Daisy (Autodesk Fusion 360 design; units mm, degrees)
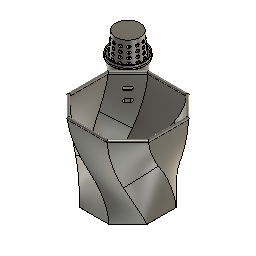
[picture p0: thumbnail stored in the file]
parameter "wall" = 1.35
parameter "height" = 77 (= "Size * 0.7") comment "Vase Hight (Medium setting)"
parameter "tolerance" = 0.15
sketch "Sketch1" plane through (0, 0, 0) normal (0, 0, 1) x axis (1, 0, 0)
  line L1 (-56.3193, -56.3193) -> (56.3193, -56.3193)
  line L2 (-56.3193, 56.3193) -> (-56.3193, -56.3193)
  line L3 (56.3193, 56.3193) -> (-56.3193, 56.3193)
  line L4 (56.3193, -56.3193) -> (56.3193, 56.3193)
  line L5 (-56.3193, 56.3193) -> (56.3193, -56.3193)
  line L6 (56.3193, 56.3193) -> (-56.3193, -56.3193)
  line L7 (-52.7837, 59.8548) -> (59.8548, -52.7837)
  line L8 (-59.8548, 52.7837) -> (52.7837, -59.8548)
  line L9 (-44.8807, -1.3193) -> (1.3193, 44.8807)
  line L10 (1.3193, -47.5193) -> (-44.8807, -1.3193)
  line L11 (47.5193, -1.3193) -> (1.3193, -47.5193)
  line L12 (1.3193, 44.8807) -> (47.5193, -1.3193)
  line L13 (1.3193, -47.5193) -> (1.3193, 44.8807)
  line L14 (47.5193, -1.3193) -> (-44.8807, -1.3193)
  line L15 (1.3193, 56.3193) -> (1.3193, -1.3193)
  line L16 (4.8548, 2.2163) -> (-2.2163, -4.8548)
  line L17 (-37.7837, 44.8548) -> (-44.8548, 37.7837)
  circle C1 centre (1.3193, -1.3193) radius 55
  circle C2 centre (-41.3193, 41.3193) radius 15
  circle C3 centre (1.3193, -1.3193) radius 46.2
  circle C4 centre (-41.3193, 41.3193) radius 13.65
  circle C5 centre (-41.3193, 41.3193) radius 13.5
  circle C6 centre (1.3193, -1.3193) radius 45.3
  point P6 (0, 0)
  point P1 (0, 0)
  point P7 (1.3193, -1.3193)
  point P8 (-41.3193, 41.3193)
  point P9 (1.3193, -1.3193)
  point P19 (1.3193, -1.3193)
  point P15 (1.3193, 44.8807)
  point P20 (1.3193, -1.3193)
  point P21 (1.3193, 56.3193)
  point P22 (-2.2163, -4.8548)
  point P23 (4.8548, 2.2163)
  point P26 (1.3193, -1.3193)
  point P27 (-44.8548, 37.7837)
  point P28 (-37.7837, 44.8548)
  point P24 (-41.3193, 41.3193)
  horizontal L1
  perpendicular L1 L2
  parallel L1 L3
  parallel L2 L4
  coincident L5 P6
  coincident L6 P6
  coincident P1 P6
  coincident L5 P7
  coincident L5 P8
  tangent L3 C2
  tangent L4 C1
  coincident P7 P9
  perpendicular L9 L10
  parallel L9 L11
  parallel L10 L12
  coincident L13 P19
  coincident L14 P19
  coincident P9 P19
  equal L9 L12
  coincident C3 P15
  coincident P9 P20
  coincident L3 P21
  perpendicular L3 L15
  coincident L8 P22
  coincident L7 P23
  perpendicular L7 L16
  equal L2 L3
  midpoint P19 L16
  coincident P19 P26
  tangent C2 C6
  coincident L8 P27
  coincident L7 P28
  perpendicular L7 L17
  coincident P24 L17
  dimension "Size" diameter C1 = 110
  dimension "d5" diameter C2 = 30
  dimension "d8" = 5
  dimension "d9" = -5
  dimension "d16" = -8.8 (= "-Size * 0.08")
  dimension "d17" angle L13 L15 = 0
  dimension "d81" distance P7 P8 = 60.3 (= "Size * 0.45 + ( wall * 8 )")
work_plane "WorkPlane1" AlongDistance 38.5 (= "height / 2")
work_plane "WorkPlane2" AlongDistance 77 (= "height")
work_plane "WorkPlane5" AlongDistance 46.2 (= "height * 0.6")
work_plane "WorkPlane4" RotateAngle 90
sketch "Sketch2" plane through (0, 0, 38.5) normal (0, 0, 1) x axis (1, 0, 0)
  line L1 (1.3193, 53.6807) -> (1.3193, -1.3193)
  line L2 (-40.5964, 22.8807) -> (25.5193, 40.5964)
  line L3 (-22.8807, -43.2349) -> (-40.5964, 22.8807)
  line L4 (43.2349, -25.5193) -> (-22.8807, -43.2349)
  line L5 (25.5193, 40.5964) -> (43.2349, -25.5193)
  line L6 (-22.8807, -43.2349) -> (25.5193, 40.5964)
  line L7 (43.2349, -25.5193) -> (-40.5964, 22.8807)
  circle C1 centre (1.3193, -1.3193) radius 55
  circle C2 centre (1.3193, -1.3193) radius 48.4
  point P2 (1.3193, -1.3193)
  point P4 (1.3193, -1.3193)
  point P5 (1.3193, 53.6807)
  point P10 (1.3193, -1.3193)
  point P6 (25.5193, 40.5964)
  coincident P2 P4
  coincident C1 P5
  vertical L1
  perpendicular L2 L3
  parallel L2 L4
  parallel L3 L5
  coincident L6 P10
  coincident L7 P10
  coincident P2 P10
  equal L2 L5
  coincident C2 P6
  dimension "d14" = -6.6 (= "-Size * 0.06")
  dimension "d15" angle L1 L6 = 30
sketch "Sketch3" plane through (0, 0, 77) normal (0, 0, 1) x axis (1, 0, 0)
  line L1 (-37.5716, 37.5716) -> (40.2101, 37.5716)
  line L2 (-37.5716, -40.2101) -> (-37.5716, 37.5716)
  line L3 (40.2101, -40.2101) -> (-37.5716, -40.2101)
  line L4 (40.2101, 37.5716) -> (40.2101, -40.2101)
  line L5 (-37.5716, -40.2101) -> (40.2101, 37.5716)
  line L6 (40.2101, -40.2101) -> (-37.5716, 37.5716)
  line L7 (1.3193, 53.6807) -> (1.3193, -1.3193)
  circle C1 centre (1.3193, -1.3193) radius 55
  circle C2 centre (-41.3193, 41.3193) radius 15
  circle C3 centre (-41.3193, 41.3193) radius 7.5
  point P7 (1.3193, -1.3193)
  point P2 (1.3193, -1.3193)
  point P3 (40.2101, 37.5716)
  point P8 (1.3193, -1.3193)
  point P9 (1.3193, 53.6807)
  perpendicular L1 L2
  parallel L1 L3
  parallel L2 L4
  coincident L5 P7
  coincident L6 P7
  coincident P2 P7
  equal L1 L4
  coincident C1 P3
  coincident P2 P8
  coincident C1 P9
  vertical L7
  concentric C2 C3
  dimension "d18" angle L5 L7 = 45
  dimension "d126" diameter C3 = 15
sketch "Sketch9" plane through (0, 0, 46.2) normal (0, 0, 1) x axis (1, 0, 0)
  circle C1 centre (-41.3193, 41.3193) radius 13.65
  circle C2 centre (-41.3193, 41.3193) radius 11
  concentric C1 C2
  dimension "d127" diameter C2 = 22
loft "Loft2" sketch "Sketch1" + "Sketch9" + "Sketch3" Start Weight 4.0298 Start TakeOff Angle 0 End Weight -3.9427 End TakeOff Angle 0
loft "Loft1" sketch "Sketch1" + "Sketch2" + "Sketch3" Start Weight 1.991 Start TakeOff Angle 0 End Weight -1.8239 End TakeOff Angle 0
chamfer "Chamfer4" distance 19.8 (= "Size * 0.18")
extrude "Extrude2" new body sketch "Sketch1" profile of C1 C2 L7 L8 C3 L9 L10 L16 C4 C5 C6 L17 blind 15 from offset 3
extrude "Extrude3" sketch "Sketch1" profile of C1 C2 L7 L8 C3 L9 L10 L16 C4 C5 C6 L17 blind -15 from offset -10
chamfer "Chamfer1" distance 1.35 (= "wall")
fillet "Fillet1" radius 3
extrude "Extrude17" sketch "Sketch1" profile of C1 L7 L8 C5 blind 20 taper -5
shell "Shell1" innerThickness 1.35 (= "wall")
extrude "Extrude18" add sketch "Sketch1" profile of C1 C2 L7 L8 C4 C5 along normal blind 20 taper -3
extrude "Extrude16" cut sketch "Sketch1" profile of C1 L7 L8 C4 C5 along normal blind 20 taper -5
offset_faces "OffsetFaces5" distance 1.35 (= "wall")
sketch "Sketch6" plane through (0, 0, 77) normal (0, 0, 1) x axis (-1, 0, 0)
  line L1 (41.3193, -24.8193) -> (41.3193, -57.8193)
  line L2 (33.6513, -26.7092) -> (48.9872, -55.9293)
  line L3 (27.74, -31.9462) -> (54.8985, -50.6923)
  line L4 (24.9396, -39.3304) -> (57.699, -43.3081)
  line L5 (25.8915, -47.1703) -> (56.747, -35.4683)
  line L6 (30.3777, -53.6697) -> (52.2608, -28.9688)
  line L7 (37.3706, -57.3398) -> (45.268, -25.2987)
  line L8 (45.268, -57.3398) -> (37.3706, -25.2987)
  line L9 (52.2608, -53.6697) -> (30.3777, -28.9688)
  line L10 (56.747, -47.1703) -> (25.8915, -35.4683)
  line L11 (57.699, -39.3304) -> (24.9396, -43.3081)
  line L12 (54.8985, -31.9462) -> (27.74, -50.6923)
  line L13 (48.9872, -26.7092) -> (33.6513, -55.9293)
  circle C1 centre (41.3193, -41.3193) radius 15.15
  circle C2 centre (41.3193, -41.3193) radius 16.5
  circle C3 centre (41.3193, -41.3193) radius 12.3
  circle C4 centre (41.3193, -41.3193) radius 15
  circle C5 centre (41.3193, -41.3193) radius 13.65
  point P5 (41.3193, -57.8193)
  point P6 (41.3193, -24.8193)
  point P3 (41.3193, -41.3193)
  coincident C2 P5
  coincident C2 P6
  vertical L1
  coincident P3 L1
  concentric C2 C4
  concentric C3 C5
  dimension "d115" distance C1 C2 = 1.35 (= "wall")
  dimension "d140" distance C1 C4 = 0.15 (= "tolerance")
  dimension "d141" distance C3 C5 = 1.35 (= "wall")
  dimension "d74" C-Pattern1-Angle = 360
extrude "Extrude7" add sketch "Sketch6" profile of C1 C2 C3 L1 L2 L3 L4 L5 L6 L7 L8 L9 L10 L11 L12 L13 no distance stored
extrude "Extrude6" add sketch "Sketch6" profile of C1 C2 L1 L2 L3 L4 L5 L6 L7 L8 L9 L10 L11 L12 L13 along normal blind 2 taper -5
extrude "Extrude8" cut sketch "Sketch6" profile of C3 L1 L2 L3 L4 L5 L6 L7 L8 L9 L10 L11 L12 L13 C5 along normal blind 2.5
rectangular_pattern "R-Pattern1" uSpaceDistance 4.5 vSpaceDistance 0
chamfer "Chamfer5" distance 0.8
circular_pattern "C-Pattern1" countU 13 TotalAngle 360
chamfer "Chamfer7" distance 2.7 (= "wall * 2") distance 1.5 (= "wall + tolerance")
sketch "Sketch7" plane through (1.3193, -1.3193, 0) normal (0.7071, -0.7071, 0) x axis (0.7071, 0.7071, 0)
  line L1 (3.65, 6) -> (3.65, 15)
  line L2 (-3.65, 15) -> (-3.65, 6)
  line L3 (5, 15) -> (5, 6)
  line L4 (-5, 6) -> (-5, 15)
  line L5 (-3.65, 64) -> (-3.65, 55)
  line L6 (3.65, 55) -> (3.65, 64)
  line L7 (5, 64) -> (5, 55)
  line L8 (-5, 55) -> (-5, 64)
  line L9 (-2, 4.35) -> (2, 4.35)
  line L10 (2, 16.65) -> (-2, 16.65)
  line L11 (2, 3) -> (-2, 3)
  line L12 (-2, 18) -> (2, 18)
  line L13 (-2, 53.35) -> (2, 53.35)
  line L14 (2, 65.65) -> (-2, 65.65)
  line L15 (-2, 67) -> (2, 67)
  line L16 (2, 52) -> (-2, 52)
  line L17 (2, 55) -> (-2, 64)
  line L18 (2, 6) -> (-2, 15)
  line L19 (2, 62.35) -> (-2, 62.35)
  line L20 (2, 56.65) -> (-2, 56.65)
  line L21 (2, 13.35) -> (-2, 13.35)
  line L22 (2, 7.65) -> (-2, 7.65)
  arc A1 centre (-2, 6) radius 1.65 clockwise from (-2, 4.35) to (-3.65, 6)
  arc A2 centre (-2, 15) radius 1.65 clockwise from (-3.65, 15) to (-2, 16.65)
  arc A3 centre (-2, 6) radius 3 clockwise from (-2, 3) to (-5, 6)
  arc A4 centre (-2, 15) radius 3 clockwise from (-5, 15) to (-2, 18)
  arc A5 centre (2, 55) radius 1.65 clockwise from (3.65, 55) to (2, 53.35)
  arc A6 centre (2, 64) radius 1.65 clockwise from (2, 65.65) to (3.65, 64)
  arc A7 centre (2, 55) radius 3 clockwise from (5, 55) to (2, 52)
  arc A8 centre (2, 64) radius 3 clockwise from (2, 67) to (5, 64)
  arc A9 centre (2, 6) radius 1.65 clockwise from (3.65, 6) to (2, 4.35)
  arc A10 centre (2, 15) radius 1.65 clockwise from (2, 16.65) to (3.65, 15)
  arc A11 centre (2, 6) radius 3 clockwise from (5, 6) to (2, 3)
  arc A12 centre (2, 15) radius 3 clockwise from (2, 18) to (5, 15)
  arc A13 centre (-2, 55) radius 1.65 clockwise from (-2, 53.35) to (-3.65, 55)
  arc A14 centre (-2, 64) radius 1.65 clockwise from (-3.65, 64) to (-2, 65.65)
  arc A15 centre (-2, 64) radius 3 clockwise from (-5, 64) to (-2, 67)
  arc A16 centre (-2, 55) radius 3 clockwise from (-2, 52) to (-5, 55)
  circle C1 centre (2, 64) radius 1.65
  circle C2 centre (-2, 64) radius 1.65
  circle C3 centre (-2, 55) radius 1.65
  circle C4 centre (2, 55) radius 1.65
  circle C5 centre (0, 59.5) radius 1.65
  circle C6 centre (2, 15) radius 1.65
  circle C7 centre (-2, 15) radius 1.65
  circle C8 centre (-2, 6) radius 1.65
  circle C9 centre (2, 6) radius 1.65
  circle C10 centre (0, 10.5) radius 1.65
  point P39 (-2, 64)
  point P42 (-2, 64)
  point P20 (2, 55)
  point P43 (2, 55)
  point P19 (-2, 15)
  point P44 (-2, 15)
  point P27 (2, 6)
  point P45 (2, 6)
  point P49 (2, 55)
  point P50 (0, 59.5)
  point P52 (-2, 15)
  point P54 (2, 6)
  point P55 (0, 10.5)
  point P56 (-2, 62.35)
  point P57 (2, 62.35)
  point P58 (-2, 56.65)
  point P59 (2, 56.65)
  point P60 (-2, 13.35)
  point P61 (2, 13.35)
  point P62 (-2, 7.65)
  point P63 (2, 7.65)
  point P11 (2, 65.65)
  point P18 (-2, 6)
  point P53 (-2, 6)
  coincident P39 P42
  coincident P20 P43
  coincident P19 P44
  coincident P27 P45
  concentric A6 C1
  concentric A14 C2
  concentric A13 C3
  coincident P43 P49
  midpoint L17 P50
  concentric A10 C6
  coincident P44 P52
  coincident P45 P54
  midpoint L18 P55
  equal C1 C2
  equal C1 C5
  equal C1 C4
  equal C1 C3
  equal C1 C6
  equal C1 C7
  equal C1 C10
  equal C1 C9
  equal C1 C8
  coincident C2 P56
  coincident C1 P57
  tangent C1 L19
  horizontal L19
  coincident C3 P58
  coincident C4 P59
  tangent C4 L20
  parallel L19 L20
  coincident C7 P60
  coincident C6 P61
  tangent C6 L21
  parallel L20 L21
  coincident C8 P62
  coincident C9 P63
  tangent C9 L22
  parallel L21 L22
  coincident P11 C1
  coincident P18 P53
extrude "Extrude19" cut sketch "Sketch7" profile of L1 L2 L5 L6 A1 A2 A5 A6 A9 L9 L10 A10 L13 A13 A14 L14 C1 C2 C3 C4 C5 C6 C7 C8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 against normal blind 60.3 (magnitude of "-d81")
extrude "Extrude14" cut sketch "Sketch7" profile of A1 A2 A5 A6 A9 L9 L10 A10 L13 A13 A14 L14 C1 C2 C3 C4 C6 C7 C8 C9 L19 L20 L21 L22 against normal blind 55 (magnitude of "-Size / 2")
combine "Combine6"
remove_body "RemoveBody28"
remove_body "RemoveBody29"
combine "Combine7"
remove_body "RemoveBody25"
remove_body "RemoveBody27"
sketch "Sketch8" plane through (0, 0, 0) normal (0.7071, 0.7071, 0) x axis (-0.7071, 0.7071, 0)
  line L1 (70.0867, 55.9399) -> (47.8978, 52.0274)
  line L2 (43.0145, 66.35) -> (129.1256, 66.35)
  line L3 (70.0867, 55.9399) -> (70.0867, 57.3107)
  line L4 (70.0867, 57.3107) -> (47.6246, 53.35)
  curve K1 (71.3958, 20) -> (72.0127, 72.9508)
  curve K2 (47.6246, 53.35) -> (45.4727, 20)
  curve K3 (44.8559, 72.9508) -> (45.4033, 65.65)
  line L5 (35.7722, 52) -> (36.2615, 52)
  line L6 (36.4887, 53.35) -> (36.0353, 53.35)
  point P6 (70.0867, 57.3107)
  point P5 (47.6246, 53.35)
  point P10 (47.6246, 53.35)
  point P13 (47.8978, 52.0274)
  point P2 (129.1256, 66.35)
  horizontal L2
  parallel L1 L4
  vertical L3
  coincident P6 K1
  coincident P5 P10
  coincident K2 P13
  coincident P2 L1
  dimension "d84" angle L1 L2 = 10
  dimension "d136" distance L1 L4 = 1.35 (= "wall")
extrude "Extrude11" new body sketch "Sketch8" profile of L1 L3 L4 distance 20
combine "Combine5"
remove_body "RemoveBody9"
remove_body "RemoveBody14"
work_plane "WorkPlane3" RotateAngle 90
sketch "Sketch5" plane through (1.3193, 30, 100) normal (1, 0, 0) x axis (0, 1, 0)
  line L1 (6.2216, -23) -> (7.5716, -23)
  line L2 (6.8966, -23.8) -> (6.8966, -23)
  circle C1 centre (6.8966, -23.8) radius 1.25
  point P2 (7.5716, -23)
  point P8 (7.5716, -23)
  point P3 (6.2216, -23)
  point P7 (6.2216, -23)
  point P5 (6.8966, -23)
  point P4 (6.8966, -23.8)
  point P6 (6.8966, -23.8)
  coincident P2 P8
  coincident P3 P7
  midpoint L1 P5
  perpendicular L1 L2
  coincident P4 P6
  dimension "d36" diameter C1 = 2.5
  dimension "d135" distance P5 P6 = 0.8
sweep "Sweep1" sketch "Sketch5" TwistAngle 0 TaperAngle 0
combine "Combine8"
